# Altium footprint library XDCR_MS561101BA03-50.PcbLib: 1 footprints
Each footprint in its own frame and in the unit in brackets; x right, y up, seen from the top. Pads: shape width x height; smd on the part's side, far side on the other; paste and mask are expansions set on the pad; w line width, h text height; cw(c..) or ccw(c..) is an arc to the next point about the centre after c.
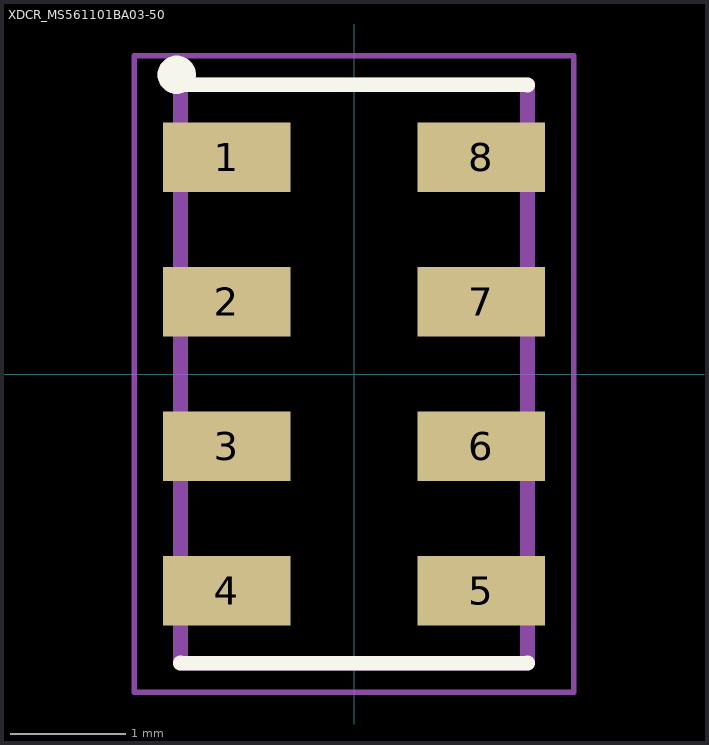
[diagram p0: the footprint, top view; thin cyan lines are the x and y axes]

## XDCR_MS561101BA03-50 [mm]
height 1.1
pads (8):
  rect 1.1x0.6 smd: 1(-1.1,1.875) 2(-1.1,0.625) 3(-1.1,-0.625) 4(-1.1,-1.875) 5(1.1,-1.875) 6(1.1,-0.625) 7(1.1,0.625) 8(1.1,1.875)
Top Overlay:
  circle w0.178: c-1.532,2.586 r0.076
  lines w0.127: -1.5,-2.495 -1.5,-2.5 1.5,-2.5 1.5,-2.495 ; -1.5,2.495 -1.5,2.5 1.5,2.5 1.5,2.495
Mechanical 13:
  circle w0.178: c-1.532,2.586 r0.076
  lines w0.127: -1.5,-2.5 1.5,-2.5 1.5,2.5 -1.5,2.5 -1.5,-2.5
Mechanical 15:
  lines w0.05: -1.9,-2.75 1.9,-2.75 1.9,2.75 -1.9,2.75 -1.9,-2.75
3D body "step_temp.STEP": height 1, standoff 0, extent -1.5,-2.5 1.5,2.5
